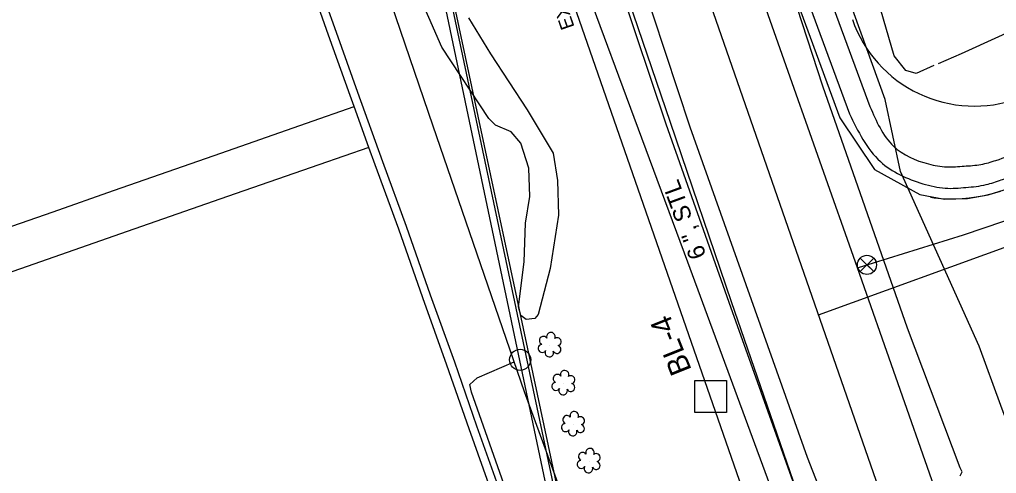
# Model space of a CAD drawing. Extents: x 1614427 to 1617186, y 896524 to 905462.
# Drawn here: x 1616155.2 to 1616382.3, y 903569 to 903674.6 of the extents above; entities that cross this region are included whole.
import ezdxf

# ---------------------------------------------------------------- set-up
doc = ezdxf.new("R2010")
doc.units = 0
for name, color, linetype in [('CTL Secondary Horizontal and Vertical CELL', 7, 'Continuous'), ('CTL Secondary Horizontal and Vertical Text', 7, 'Continuous'), ('Exist Horizontal Alignment', 7, 'Continuous'), ('Exist Other Culture Fence Line', 7, 'Continuous'), ('Exist Right of Way Easement Line', 7, 'Continuous'), ('Exist Right of Way Line', 7, 'Continuous'), ('Exist Right of Way Line Text', 7, 'Continuous'), ('Exist Roads Change in Surface', 7, 'Continuous'), ('Exist Roads Curbs', 7, 'Continuous'), ('Exist Roads EOP', 7, 'Continuous'), ('Exist Roads EOP Other', 7, 'Continuous'), ('Exist Roads EOT', 7, 'Continuous'), ('Exist Utilities Gas UG Line SUE LOS B', 7, 'Continuous'), ('Exist Utilities Gas UG Line SUE LOS B Text', 7, 'Continuous'), ('Exist Utilities Other Pole CELL', 7, 'Continuous'), ('Exist Utilities Power UG Cable SUE LOS B', 7, 'Continuous'), ('Exist Utilities Power UG Cable SUE LOS D', 7, 'Continuous'), ('Exist Utilities Telephone UG Cable SUE LOS B', 7, 'Continuous'), ('Exist Utilities Telephone UG FO SUE LOS B', 7, 'Continuous'), ('Exist Utilities TV UG Cable SUE LOS D', 7, 'Continuous'), ('Exist Utilities Water UG Line SUE LOS B', 7, 'Continuous'), ('Exist Utilities Water Valve CELL', 7, 'Continuous'), ('Exist Vegetation Hedge Row', 7, 'Continuous'), ('Exist Vegetation Shrub CELL', 7, 'Continuous')]:
    doc.layers.add(name, color=color, linetype=linetype)

# ---------------------------------------------------------------- blocks, each defined once
blk = doc.blocks.new('CTL SECONDARY HORIZONTAL AND VERTICAL')
at = {"layer": 'CTL Secondary Horizontal and Vertical CELL'}
blk.add_line((0, 0), (0, 0), dxfattribs=at)
blk.add_lwpolyline([(-0.1043, 0.0004), (0.0005, 0.1052), (0.1055, 0.0002), (0.0007, -0.1047)], close=True, dxfattribs=at)
blk = doc.blocks.new('EXIST UTILITIES WATER VALVE')
at = {"layer": 'Exist Utilities Water Valve CELL'}
blk.add_lwpolyline([(0.0315, 0.0315), (-0.0315, -0.0315), (0, 0), (0.0315, -0.0315), (-0.0315, 0.0315)], dxfattribs=at)
blk.add_circle((0, 0), 0.0445, dxfattribs=at)

msp = doc.modelspace()

# ---------------------------------------------------------------- linework, layer by layer
at = {"layer": 'Exist Horizontal Alignment'}
for p, q in [((1616576.74, 902927.89), (1616238.24, 903901.21)), ((1616340.93, 903605.93), (1616526.35, 903673.17)), ((1616340.93, 903605.93), (1616526.35, 903673.17))]:
    msp.add_line(p, q, dxfattribs=at)
at = {"layer": 'Exist Other Culture Fence Line'}
msp.add_lwpolyline([(1616340.29, 903264.26), (1616332.08, 903290.24), (1616316.67, 903338.32), (1616302.47, 903379.06), (1616267.37, 903366.34), (1616220.02, 903349.18), (1616202.8, 903398.78), (1616185.25, 903447.61), (1616177.66, 903469.59), (1616182.75, 903471.48), (1616219.13, 903484.56), (1616299.32, 903513.96), (1616290.54, 903538.93), (1616272.63, 903588.03), (1616251.39, 903649.78), (1616231.78, 903707.31), (1616211.35, 903767.58)], dxfattribs=at)
at = {"layer": 'Exist Right of Way Easement Line'}
msp.add_arc((1616377.14, 903684.48), 30, 199.1768, 289.9333, dxfattribs=at)
at = {"layer": 'Exist Right of Way Line'}
for p, q in [((1615887.44, 905426.15), (1616864.55, 900788.06)), ((1616548.32, 902918.27), (1616209.91, 903891.34))]:
    msp.add_line(p, q, dxfattribs=at)
at = {"layer": 'Exist Roads Change in Surface'}
for points in [[(1616108.1, 903610.72), (1616117.38, 903613.98), (1616142.18, 903622.65), (1616163.07, 903629.88), (1616177.06, 903634.82), (1616200.42, 903642.96), (1616221.92, 903650.51), (1616233.01, 903654.38)], [(1616236.41, 903644.88), (1616224.78, 903640.85), (1616203.53, 903633.48), (1616180.2, 903625.29), (1616160.1, 903618.3), (1616140.93, 903611.63), (1616121.49, 903604.78), (1616112.78, 903601.76)]]:
    msp.add_lwpolyline(points, dxfattribs=at)
at = {"layer": 'Exist Roads Curbs'}
for points in [[(1616266.96, 903564.82), (1616261.52, 903580.04), (1616256.36, 903594.89), (1616250.78, 903610.5), (1616245.15, 903626.51), (1616239.64, 903641.51), (1616233.87, 903657.61), (1616228.87, 903671.59), (1616223.77, 903685.94), (1616218.3, 903701.18), (1616213.09, 903715.7), (1616207.52, 903731.14), (1616201.4, 903748.42), (1616195.63, 903764.68)], [(1616318.06, 903734.3), (1616332.7, 903694.56), (1616348.12, 903652.72)]]:
    msp.add_lwpolyline(points, dxfattribs=at)
msp.add_spline([(1616348.12, 903652.72), (1616355.32, 903641.58), (1616365.18, 903636.44), (1616370.4, 903635.39), (1616375.21, 903635.57), (1616379.9, 903636.22), (1616383.41, 903637.33), (1616389.79, 903639.33), (1616395.51, 903641.86)], degree=3, dxfattribs=at)
at = {"layer": 'Exist Roads EOP'}
for points in [[(1616273.35, 903855.36), (1616287.12, 903815.79), (1616301.21, 903775.08), (1616315.66, 903733.58), (1616330.46, 903693.74), (1616345.85, 903651.77), (1616353.93, 903639.77), (1616364.52, 903633.91), (1616370.25, 903632.83), (1616375.59, 903632.98), (1616380.35, 903633.82), (1616384.07, 903635.01), (1616390.61, 903637.51), (1616396.32, 903640.17), (1616405.35, 903644.69), (1616422.2, 903653.39)], [(1616469.52, 903183.22), (1616456.13, 903221.35), (1616442.17, 903261), (1616431.86, 903289.89), (1616417.71, 903330.31), (1616403.14, 903371.75), (1616391.84, 903403.85), (1616377.99, 903443.03), (1616362.79, 903484.42), (1616359.81, 903491.48), (1616352.94, 903512.49), (1616348.91, 903526.89), (1616335.01, 903567.07), (1616320.18, 903608.78), (1616305.52, 903650.31), (1616294.93, 903682.02), (1616281.37, 903721.05)]]:
    msp.add_lwpolyline(points, dxfattribs=at)
at = {"layer": 'Exist Roads EOP Other'}
for points in [[(1616265.17, 903564.17), (1616259.72, 903579.41), (1616254.56, 903594.26), (1616248.98, 903609.86), (1616243.35, 903625.86), (1616237.85, 903640.86), (1616236.41, 903644.88), (1616233.01, 903654.38), (1616232.08, 903656.97), (1616227.07, 903670.95), (1616221.98, 903685.3), (1616216.51, 903700.53), (1616211.3, 903715.06), (1616205.72, 903730.5), (1616199.6, 903747.78), (1616196.01, 903757.85), (1616192.57, 903767.41), (1616191.39, 903770.68)], [(1616322.72, 903736.06), (1616337.4, 903696.46), (1616352.89, 903654.39)], [(1616383.12, 903634.62), (1616381.28, 903634.09), (1616379.41, 903633.64), (1616377.57, 903633.28), (1616375.96, 903633.04), (1616374.33, 903632.89), (1616372.7, 903632.82), (1616371.07, 903632.83), (1616369.44, 903632.91), (1616367.82, 903633.08), (1616366.99, 903633.2)]]:
    msp.add_lwpolyline(points, dxfattribs=at)
msp.add_spline([(1616352.89, 903654.39), (1616358.39, 903645.16), (1616366.51, 903641.02), (1616370.72, 903640.35), (1616374.8, 903640.53), (1616378.7, 903640.91), (1616382.15, 903641.86), (1616387.98, 903643.96), (1616393.22, 903646.32)], degree=3, dxfattribs=at)
at = {"layer": 'Exist Roads EOT'}
msp.add_lwpolyline([(1616470.84, 903183.57), (1616457.44, 903221.88), (1616443.4, 903261.41), (1616433.06, 903290.44), (1616418.78, 903330.63), (1616404.11, 903372.11), (1616392.67, 903404.15), (1616378.77, 903443.28), (1616364.13, 903484.9), (1616349.34, 903527.05), (1616335.12, 903567.18), (1616320.68, 903608.97), (1616306.55, 903650.64), (1616295.77, 903682.27), (1616282.46, 903721.52)], dxfattribs=at)
at = {"layer": 'Exist Utilities Gas UG Line SUE LOS B'}
msp.add_lwpolyline([(1616588.83, 902805.4), (1616574.94, 902856.71), (1616560.06, 902902.39), (1616552.18, 902925.27), (1616536.08, 902973.65), (1616521.52, 903015.88), (1616492.41, 903100.65), (1616481.17, 903130.4), (1616470.48, 903162.66), (1616450.18, 903220.6), (1616431.22, 903276.51), (1616418.49, 903313.39), (1616364.61, 903464.71), (1616350.51, 903509.73), (1616310.55, 903618.21), (1616275.13, 903713.81), (1616252.85, 903771.73), (1616229.48, 903831.39), (1616218.51, 903860.65)], dxfattribs=at)
at = {"layer": 'Exist Utilities Other Pole CELL'}
msp.add_circle((1616271.58, 903595.48), 2.46, dxfattribs=at)
at = {"layer": 'Exist Utilities Power UG Cable SUE LOS B'}
msp.add_lwpolyline([(1616078.39, 903444.91), (1616080.79, 903445.79), (1616111.9, 903456.51), (1616150.47, 903470.19), (1616172.13, 903476.77), (1616191.74, 903485.56), (1616218.83, 903494.34), (1616221.19, 903493.99), (1616221.74, 903493.66), (1616222.54, 903493.68), (1616224.9, 903496.09), (1616227.88, 903498.43), (1616257.85, 903508.64), (1616284.87, 903518.71), (1616284.56, 903521.12), (1616268.26, 903565.29), (1616260.26, 903587.97), (1616259.89, 903589.77), (1616261.58, 903591.25), (1616270.2, 903594.97)], dxfattribs=at)
at = {"layer": 'Exist Utilities Power UG Cable SUE LOS D'}
msp.add_lwpolyline([(1616526.22, 902383.26), (1616457.17, 902711.3), (1616419.34, 902888.36), (1616377.66, 903092.6), (1616374.57, 903105.22), (1616359.69, 903168.7), (1616334, 903297.9), (1616293.26, 903491.82), (1616271.51, 903595.33), (1616239.2, 903749.12)], dxfattribs=at)
at = {"layer": 'Exist Utilities Telephone UG Cable SUE LOS B'}
for points in [[(1616341.13, 903526.17), (1616350.06, 903524.57), (1616353.18, 903523.97), (1616354.27, 903525.62), (1616354.2, 903527.32), (1616352.41, 903531.49), (1616346.51, 903551.88), (1616338.38, 903572.73), (1616311.12, 903649.59), (1616299.64, 903684.42), (1616264.73, 903785.56), (1616225.23, 903895.34)], [(1616373.87, 903568.46), (1616374.3, 903569.41), (1616373.86, 903570.39), (1616361.62, 903602.86), (1616341.95, 903659.09), (1616330.11, 903695.59), (1616311.83, 903747.03), (1616311.46, 903750.28), (1616313.05, 903753.14), (1616316.41, 903754.31), (1616347.19, 903767.38), (1616362.66, 903772.42), (1616371.42, 903776.41)]]:
    msp.add_lwpolyline(points, dxfattribs=at)
at = {"layer": 'Exist Utilities Telephone UG FO SUE LOS B'}
for points in [[(1616519.36, 903185.77), (1616513.96, 903203.22), (1616503.76, 903233.09), (1616503.75, 903233.09), (1616489.07, 903279.68), (1616470.01, 903336.66), (1616452.34, 903386.43), (1616440.14, 903425.32), (1616426.94, 903455.24), (1616423.27, 903466.29), (1616413.77, 903500.18), (1616402.08, 903534.75), (1616383.28, 903584.85), (1616378.31, 903598.68), (1616360.02, 903639.24), (1616356.39, 903655.99), (1616340.68, 903699.57), (1616327.33, 903739.18), (1616327.34, 903739.18), (1616313.72, 903781.55), (1616301.65, 903812.03), (1616292.8, 903840.69)], [(1616367.72, 903663.9), (1616363.6, 903662.09), (1616361.25, 903662.79), (1616358.51, 903666.15), (1616344.89, 903713.16), (1616335.76, 903744.87), (1616330.15, 903772.43), (1616325.41, 903800.74), (1616321.6, 903818.31), (1616318.76, 903827.11), (1616315.94, 903831.79), (1616312.59, 903834.29), (1616307.67, 903834.34)], [(1616368.82, 903664.38), (1616374.13, 903666.7), (1616400.24, 903678.58), (1616424.15, 903688.58), (1616451.87, 903697.49), (1616492.43, 903711.43), (1616524.09, 903720.83), (1616535.63, 903725.41), (1616539.88, 903728.72), (1616540.44, 903740.67), (1616541.79, 903762.56), (1616543.01, 903774.12), (1616544.39, 903782.9), (1616550.25, 903790.71), (1616577.87, 903805.8), (1616588.44, 903809.04)]]:
    msp.add_lwpolyline(points, dxfattribs=at)
at = {"layer": 'Exist Utilities TV UG Cable SUE LOS D'}
msp.add_lwpolyline([(1616295.86, 903492.41), (1616273.81, 903595.89), (1616240.99, 903749.89), (1616178.16, 903933.06), (1616083.67, 904205.09), (1616028.66, 904363.47)], dxfattribs=at)
at = {"layer": 'Exist Utilities Water UG Line SUE LOS B'}
for points in [[(1616526.94, 903118.95), (1616504.59, 903181.23), (1616480.02, 903252.46), (1616446.17, 903345), (1616411.28, 903445.17), (1616385.62, 903515.15), (1616350.02, 903616.87), (1616323.73, 903691.37), (1616291.21, 903786.26), (1616260.45, 903872.07), (1616224.66, 903974.02), (1616192.08, 904066.13), (1616173.94, 904118.11), (1616130.42, 904237.78), (1616097.26, 904331.65), (1616083.48, 904374.45), (1616069.85, 904420.53), (1616059.14, 904458.49), (1616050.85, 904496.39), (1616045.84, 904527.76), (1616030.28, 904669.9)], [(1616350.21, 903616.94), (1616374.62, 903624.54), (1616426.35, 903642.07), (1616478.57, 903660.36), (1616520.74, 903675.61), (1616534.8, 903680.84), (1616536.9, 903682.38), (1616549.12, 903691.48), (1616560.45, 903718.95), (1616573.2, 903736.65), (1616589.15, 903758.02), (1616604.81, 903760.79)]]:
    msp.add_lwpolyline(points, dxfattribs=at)
at = {"layer": 'Exist Vegetation Hedge Row'}
for points in [[(1616272.49, 903618.23), (1616272.8, 903627.29), (1616273.83, 903633.43), (1616273.57, 903640.03), (1616271.74, 903645.85), (1616269.46, 903648.5), (1616265.87, 903650.04), (1616264.27, 903651.59), (1616253.34, 903668.19), (1616247.35, 903682.05)], [(1616259.55, 903674.99), (1616264.72, 903666.63), (1616273.18, 903653.58), (1616279.23, 903643.56), (1616280.23, 903637.19), (1616280.46, 903629.12), (1616278.52, 903616.75), (1616275.73, 903606.01), (1616275.01, 903605.06), (1616272.95, 903604.88), (1616271.77, 903605.82), (1616271.16, 903607.83), (1616272.49, 903618.23)]]:
    msp.add_lwpolyline(points, dxfattribs=at)
at = {"layer": 'Exist Vegetation Shrub CELL'}
for p, q in [((1616278.5, 903598.82), (1616278.5, 903598.82)), ((1616281.71, 903589.98), (1616281.71, 903589.98)), ((1616283.94, 903580.43), (1616283.94, 903580.43)), ((1616287.59, 903571.85), (1616287.59, 903571.85))]:
    msp.add_line(p, q, dxfattribs=at)
for centre, radius, start, end in [((1616277.01, 903599.95), 0.968, 35.8908, 245.4216), ((1616278.72, 903600.87), 0.99, 334.8391, 200.4717), ((1616280.17, 903599.69), 0.929, 284.4567, 126.0861), ((1616276.7, 903598.12), 0.955, 95.1099, 327.9534), ((1616280.13, 903597.9), 0.937, 204.9913, 73.4601), ((1616278.37, 903597.14), 0.984, 151.2797, 21.387), ((1616280.23, 903591.11), 0.968, 35.8908, 245.4216), ((1616281.94, 903592.02), 0.99, 334.8391, 200.4717), ((1616283.38, 903590.85), 0.929, 284.4567, 126.0861), ((1616279.91, 903589.28), 0.955, 95.1099, 327.9534), ((1616281.58, 903588.3), 0.984, 151.2797, 21.387), ((1616283.35, 903589.05), 0.937, 204.9913, 73.4601), ((1616282.46, 903581.56), 0.968, 35.8908, 245.4216), ((1616284.17, 903582.47), 0.99, 334.8391, 200.4717), ((1616285.61, 903581.3), 0.929, 284.4567, 126.0861), ((1616282.14, 903579.73), 0.955, 95.1099, 327.9534), ((1616285.58, 903579.5), 0.937, 204.9913, 73.4601), ((1616283.81, 903578.75), 0.984, 151.2797, 21.387), ((1616286.1, 903572.98), 0.968, 35.8908, 245.4216), ((1616287.81, 903573.89), 0.99, 334.8391, 200.4717), ((1616289.26, 903572.72), 0.929, 284.4567, 126.0861), ((1616285.79, 903571.14), 0.955, 95.1099, 327.9534), ((1616287.46, 903570.16), 0.984, 151.2797, 21.387), ((1616289.22, 903570.92), 0.937, 204.9913, 73.4601)]:
    msp.add_arc(centre, radius, start, end, dxfattribs=at)

# ---------------------------------------------------------------- block references
at = {"layer": 'CTL Secondary Horizontal and Vertical CELL', "xscale": 50, "yscale": 49.99999999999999, "rotation": 44.99999999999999}
msp.add_blockref('CTL SECONDARY HORIZONTAL AND VERTICAL', (1616315.85, 903586.92), dxfattribs=at)
msp.add_blockref('CTL SECONDARY HORIZONTAL AND VERTICAL', (1616315.85, 903586.92), dxfattribs=at)
at = {"layer": 'Exist Utilities Water Valve CELL', "xscale": 50, "yscale": 50}
msp.add_blockref('EXIST UTILITIES WATER VALVE', (1616352.19, 903617.56), dxfattribs=at)

# ---------------------------------------------------------------- texts
at = {"layer": 'CTL Secondary Horizontal and Vertical Text'}
msp.add_text('BL-4', height=5, rotation=111.8667, dxfattribs=at).set_placement((1616311.52, 903593.14))
at = {"layer": 'Exist Right of Way Line Text'}
msp.add_text('EXISTING R/W', height=3.2, rotation=109.1768, dxfattribs=at).set_placement((1616284.26, 903672.93))
at = {"layer": 'Exist Utilities Gas UG Line SUE LOS B Text'}
msp.add_text('6 ", STL', height=4, rotation=110.2218, dxfattribs=at).set_placement((1616314.91, 903619.73))

doc.saveas('drawing.dxf')
